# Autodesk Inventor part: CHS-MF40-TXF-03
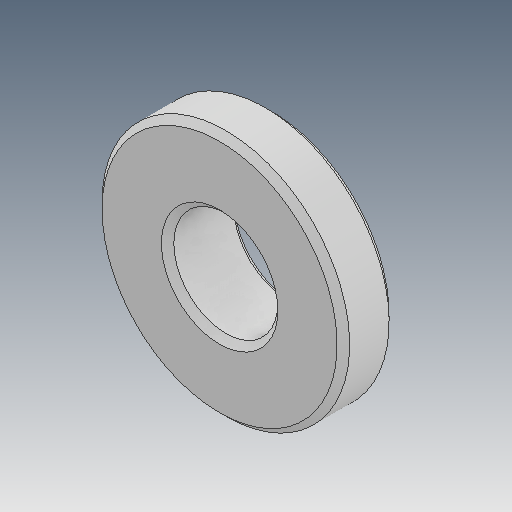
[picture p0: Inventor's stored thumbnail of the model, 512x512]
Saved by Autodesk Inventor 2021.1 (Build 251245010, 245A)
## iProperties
Created: 2019-05
Part Number: CHS-MF40-TXF-03
Material: Ogólny
Document SubType Name: Modeling
Designer: user
Density: 1 g/cm^3
Appearance: Domyślna
Author: user
Revision Number: ÈÎºÎ
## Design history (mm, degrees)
feature "ÊäÈë1"
node "Bryła1"
